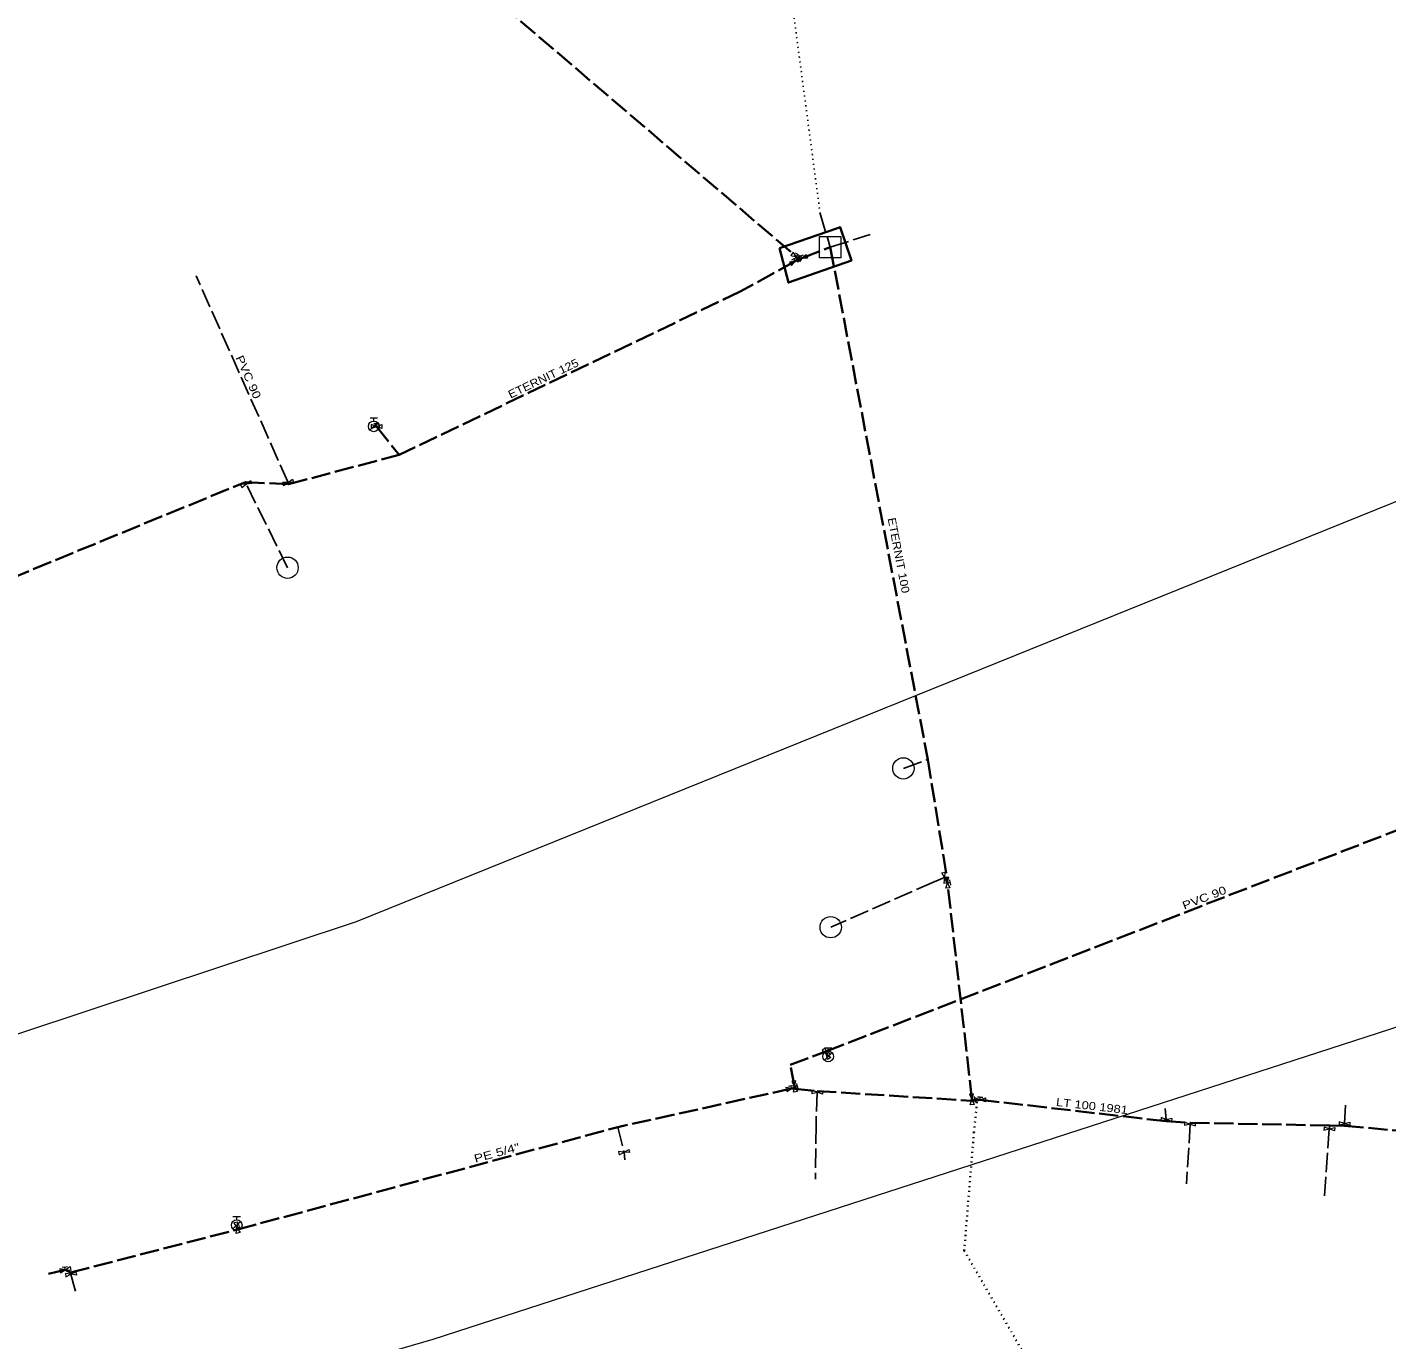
# Model space of a CAD drawing. Extents: x -616592 to -615844, y -1088988 to -1088174.
# Drawn here: x -616074.1 to -615946.8, y -1088431.2 to -1088308.2 of the extents above; entities that cross this region are included whole.
import ezdxf
from ezdxf.enums import TextEntityAlignment as Align

# ---------------------------------------------------------------- set-up
doc = ezdxf.new("R2010")
doc.units = 0
doc.header["$LTSCALE"] = 0.3
for name, pattern in [('DOTTED', [1.5, 0.3, -1.2]), ('LONG_DASHED', [7.5, 6, -1.5]), ('SHORT_DASHED', [2.7, 1.5, -1.2])]:
    doc.linetypes.add(name, pattern=pattern)
for name, color, linetype, lineweight in [('1', 7, 'Continuous', 13), ('10', 7, 'Continuous', 13), ('35', 7, 'LONG_DASHED', 35), ('36', 7, 'SHORT_DASHED', 35), ('50', 7, 'LONG_DASHED', 25), ('51', 7, 'SHORT_DASHED', 25), ('56', 7, 'Continuous', 35)]:
    doc.layers.add(name, color=color, linetype=linetype, lineweight=lineweight)
doc.layers.add('16', color=7, linetype='Continuous')
doc.layers.add('19', color=7, linetype='Continuous')

msp = doc.modelspace()

# ---------------------------------------------------------------- linework, layer by layer
at = {"layer": '1'}
msp.add_lwpolyline([(-616317.402, -1088743.479), (-616316.925, -1088623.142), (-616336.026, -1088584.94), (-616318.357, -1088562.497), (-616286.363, -1088552.469), (-616214.734, -1088468.424), (-616144.06, -1088425.447), (-616043.302, -1088392.02), (-615921.533, -1088342.835), (-615901, -1088273.116), (-615900.045, -1088185.251), (-615900.045, -1088185.251), (-615851.337, -1088190.027), (-615863.753, -1088293.172), (-615879.033, -1088367.189), (-615932.994, -1088397.75), (-616036.139, -1088431.177), (-616143.105, -1088462.216), (-616202.318, -1088518.087), (-616257.711, -1088587.328), (-616274.902, -1088683.788)], dxfattribs=at)
at = {"layer": '10'}
for p, q in [((-616002.31, -1088329.928), (-616002.527, -1088330.052)), ((-616001.936, -1088329.536), (-616002.145, -1088329.398)), ((-616001.648, -1088329.651), (-616001.879, -1088329.745)), ((-616042.024, -1088345.984), (-616041.317, -1088345.277)), ((-616042.02, -1088344.83), (-616041.32, -1088344.83)), ((-616041.67, -1088345.13), (-616041.67, -1088344.83)), ((-616041.41, -1088345.4), (-616041.66, -1088345.4)), ((-615987.671, -1088388.356), (-615987.696, -1088388.107)), ((-615999.45, -1088403.86), (-615998.75, -1088403.86)), ((-615999.034, -1088404.293), (-615999.161, -1088404.078)), ((-615999.1, -1088404.16), (-615999.1, -1088403.86)), ((-615999.454, -1088405.014), (-615998.747, -1088404.307)), ((-616002.566, -1088407.424), (-616002.812, -1088407.47)), ((-616001.994, -1088407.428), (-616002.036, -1088407.181)), ((-615985.381, -1088408.663), (-615985.398, -1088408.413)), ((-615984.85, -1088408.48), (-615985.1, -1088408.48)), ((-616054.864, -1088420.824), (-616054.157, -1088420.117)), ((-616054.86, -1088419.67), (-616054.16, -1088419.67)), ((-616054.51, -1088419.97), (-616054.51, -1088419.67)), ((-616054.246, -1088420.656), (-616054.299, -1088420.412)), ((-616070.624, -1088424.396), (-616070.868, -1088424.449))]:
    msp.add_line(p, q, dxfattribs=at)
for points in [[(-615997.9, -1088327.84), (-615997.9, -1088329.84), (-615999.9, -1088329.84), (-615999.9, -1088327.84)], [(-616053.63, -1088351.03), (-616053.215, -1088350.713), (-616053.109, -1088350.994), (-616053.63, -1088351.03), (-616054.151, -1088351.066), (-616054.045, -1088351.347)], [(-616049.7, -1088350.88), (-616049.272, -1088350.581), (-616049.178, -1088350.866), (-616049.7, -1088350.88), (-616050.222, -1088350.894), (-616050.128, -1088351.179)], [(-615988.21, -1088387.91), (-615988.449, -1088387.446), (-615988.154, -1088387.391), (-615988.21, -1088387.91), (-615988.266, -1088388.429), (-615987.971, -1088388.374)], [(-616000.13, -1088408.01), (-615999.622, -1088407.891), (-615999.64, -1088408.19), (-616000.13, -1088408.01), (-616000.62, -1088407.83), (-616000.638, -1088408.129)], [(-615967.42, -1088410.56), (-615966.91, -1088410.448), (-615966.933, -1088410.747), (-615967.42, -1088410.56), (-615967.907, -1088410.373), (-615967.93, -1088410.672)], [(-615965.17, -1088410.99), (-615965.673, -1088411.13), (-615965.667, -1088410.83), (-615965.17, -1088410.99), (-615964.673, -1088411.15), (-615964.667, -1088410.85)], [(-615952.14, -1088411.45), (-615951.633, -1088411.326), (-615951.649, -1088411.626), (-615952.14, -1088411.45), (-615952.631, -1088411.274), (-615952.647, -1088411.574)], [(-615950.71, -1088410.95), (-615950.205, -1088410.819), (-615950.216, -1088411.119), (-615950.71, -1088410.95), (-615951.204, -1088410.781), (-615951.215, -1088411.081)], [(-616018.22, -1088413.62), (-616017.759, -1088413.375), (-616017.7, -1088413.669), (-616018.22, -1088413.62), (-616018.74, -1088413.571), (-616018.681, -1088413.865)], [(-616070.05, -1088425.07), (-616069.58, -1088424.842), (-616069.532, -1088425.138), (-616070.05, -1088425.07), (-616070.568, -1088425.002), (-616070.52, -1088425.298)]]:
    msp.add_lwpolyline(points, close=True, dxfattribs=at)
for points in [[(-616002.186, -1088330.145), (-616001.844, -1088329.735), (-616001.659, -1088330.06), (-616002.186, -1088330.145), (-616002.713, -1088330.23), (-616002.528, -1088330.555), (-616002.186, -1088330.145), (-616002.31, -1088329.928), (-616002.093, -1088329.804)], [(-616002.074, -1088329.745), (-616001.554, -1088329.865), (-616001.76, -1088330.177), (-616002.074, -1088329.745), (-616002.388, -1088329.313), (-616002.595, -1088329.625), (-616002.074, -1088329.745), (-616001.936, -1088329.536), (-616001.728, -1088329.674)], [(-616001.554, -1088329.883), (-616001.16, -1088329.523), (-616001.02, -1088329.869), (-616001.554, -1088329.883), (-616002.088, -1088329.897), (-616001.948, -1088330.243), (-616001.554, -1088329.883), (-616001.648, -1088329.651), (-616001.416, -1088329.558)], [(-616041.41, -1088345.65), (-616040.91, -1088345.463), (-616040.91, -1088345.837), (-616041.41, -1088345.65), (-616041.91, -1088345.463), (-616041.91, -1088345.837), (-616041.41, -1088345.65), (-616041.41, -1088345.4), (-616041.16, -1088345.4)], [(-615987.92, -1088388.38), (-615987.685, -1088388.859), (-615988.057, -1088388.896), (-615987.92, -1088388.38), (-615987.783, -1088387.864), (-615988.155, -1088387.901), (-615987.92, -1088388.38), (-615987.671, -1088388.356), (-615987.647, -1088388.604)], [(-615999.25, -1088404.42), (-615998.835, -1088404.756), (-615999.158, -1088404.946), (-615999.25, -1088404.42), (-615999.342, -1088403.894), (-615999.665, -1088404.084), (-615999.25, -1088404.42), (-615999.034, -1088404.293), (-615998.908, -1088404.509)], [(-616002.52, -1088407.67), (-616002.063, -1088407.394), (-616001.994, -1088407.762), (-616002.52, -1088407.67), (-616003.046, -1088407.578), (-616002.977, -1088407.946), (-616002.52, -1088407.67), (-616002.566, -1088407.424), (-616002.32, -1088407.378)], [(-616002.24, -1088407.47), (-616001.971, -1088407.931), (-616002.34, -1088407.994), (-616002.24, -1088407.47), (-616002.14, -1088406.946), (-616002.509, -1088407.009), (-616002.24, -1088407.47), (-616001.994, -1088407.428), (-616001.951, -1088407.674)], [(-615985.63, -1088408.68), (-615985.409, -1088409.166), (-615985.782, -1088409.192), (-615985.63, -1088408.68), (-615985.478, -1088408.168), (-615985.851, -1088408.194), (-615985.63, -1088408.68), (-615985.381, -1088408.663), (-615985.363, -1088408.912)], [(-615984.85, -1088408.73), (-615984.35, -1088408.543), (-615984.35, -1088408.917), (-615984.85, -1088408.73), (-615985.35, -1088408.543), (-615985.35, -1088408.917), (-615984.85, -1088408.73), (-615984.85, -1088408.48), (-615984.6, -1088408.48)], [(-616054.49, -1088420.71), (-616054.2, -1088421.158), (-616054.565, -1088421.238), (-616054.49, -1088420.71), (-616054.415, -1088420.182), (-616054.78, -1088420.262), (-616054.49, -1088420.71), (-616054.246, -1088420.656), (-616054.192, -1088420.901)], [(-616070.57, -1088424.64), (-616070.122, -1088424.35), (-616070.042, -1088424.715), (-616070.57, -1088424.64), (-616071.098, -1088424.565), (-616071.018, -1088424.93), (-616070.57, -1088424.64), (-616070.624, -1088424.396), (-616070.379, -1088424.342)]]:
    msp.add_lwpolyline(points, dxfattribs=at)
for centre, radius in [((-616041.6698, -1088345.6297), 0.5), ((-616049.75, -1088358.87), 1), ((-615992.05, -1088377.67), 1), ((-615998.86, -1088392.55), 1), ((-615999.0998, -1088404.6597), 0.5), ((-616054.5098, -1088420.4697), 0.5)]:
    msp.add_circle(centre, radius, dxfattribs=at)
at = {"layer": '35'}
for p, q in [((-615998.9, -1088328.84), (-615989.76, -1088376.84)), ((-616041.67, -1088345.63), (-616041.41, -1088345.65)), ((-616041.41, -1088345.65), (-616039.3, -1088348.31)), ((-616049.66, -1088351.04), (-616039.3, -1088348.31)), ((-616104.798, -1088371.828), (-616053.69, -1088350.85)), ((-616053.69, -1088350.85), (-616049.66, -1088351.04)), ((-615999.31, -1088404.19), (-615929.43, -1088377.13)), ((-615989.76, -1088376.84), (-615987.98, -1088387.85)), ((-616002.21, -1088407.71), (-616002.24, -1088407.47)), ((-616002.21, -1088407.71), (-616000.13, -1088407.91)), ((-616000.13, -1088407.91), (-615985.64, -1088408.81)), ((-615985.64, -1088408.81), (-615985.13, -1088408.73)), ((-616054.44, -1088420.88), (-616018.79, -1088411.28)), ((-615967.44, -1088410.73), (-615965.17, -1088410.87)), ((-615965.17, -1088410.87), (-615952.1, -1088411.13)), ((-615952.1, -1088411.13), (-615950.72, -1088411.16)), ((-616054.49, -1088420.71), (-616054.51, -1088420.47)), ((-616054.44, -1088420.88), (-616054.49, -1088420.71)), ((-616070.08, -1088424.91), (-616054.44, -1088420.88)), ((-616070.57, -1088424.64), (-616072.15, -1088425.04)), ((-616070.08, -1088424.91), (-616070.57, -1088424.64))]:
    msp.add_line(p, q, dxfattribs=at)
for points in [[(-616094.121, -1088249.2), (-616041.605, -1088295.97), (-616001.79, -1088329.97)], [(-616001.79, -1088329.97), (-616001.554, -1088329.883), (-615998.9, -1088328.84)], [(-616001.79, -1088329.97), (-616002.186, -1088330.145), (-616007.34, -1088333), (-616039.3, -1088348.31)], [(-615985.64, -1088408.81), (-615985.63, -1088408.68), (-615987.92, -1088388.38), (-615987.98, -1088387.85)], [(-616002.24, -1088407.47), (-616002.66, -1088405.46), (-615999.31, -1088404.19)], [(-615999.31, -1088404.19), (-615999.25, -1088404.42), (-615999.1, -1088404.66)], [(-616002.21, -1088407.71), (-616002.52, -1088407.67), (-616018.79, -1088411.28)], [(-615967.44, -1088410.73), (-615984.85, -1088408.73), (-615985.13, -1088408.73)], [(-615950.72, -1088411.16), (-615912.516, -1088414.608), (-615902.96, -1088415.47)]]:
    msp.add_lwpolyline(points, dxfattribs=at)
at = {"layer": '36', "linetype": 'DOTTED'}
msp.add_line((-615986.346, -1088422.861), (-615949.1, -1088487.052), dxfattribs=at)
msp.add_lwpolyline([(-615986.346, -1088422.861), (-615985.44, -1088411.78), (-615985.13, -1088408.73)], dxfattribs=at)
at = {"layer": '50'}
for p, q in [((-615999.85, -1088325.68), (-615998.9, -1088328.84)), ((-615998.9, -1088328.84), (-615995.15, -1088327.66)), ((-616049.7, -1088350.88), (-616058.31, -1088331.54)), ((-616049.66, -1088351.04), (-616049.7, -1088350.88)), ((-615992.05, -1088377.67), (-615989.76, -1088376.84)), ((-615987.98, -1088387.85), (-615988.21, -1088387.91)), ((-615950.71, -1088410.95), (-615950.635, -1088409.222)), ((-615967.42, -1088410.56), (-615967.531, -1088409.545)), ((-615967.44, -1088410.73), (-615967.42, -1088410.56)), ((-616018.79, -1088411.28), (-616018.22, -1088413.62)), ((-615965.17, -1088410.99), (-615965.532, -1088416.608)), ((-615965.17, -1088410.87), (-615965.17, -1088410.99)), ((-615952.14, -1088411.45), (-615952.596, -1088418.02)), ((-615952.1, -1088411.13), (-615952.14, -1088411.45)), ((-615950.72, -1088411.16), (-615950.71, -1088410.95)), ((-616018.22, -1088413.62), (-616018.146, -1088414.355)), ((-616070.08, -1088424.91), (-616070.05, -1088425.07))]:
    msp.add_line(p, q, dxfattribs=at)
for points in [[(-616049.75, -1088358.87), (-616053.63, -1088351.03), (-616053.69, -1088350.85)], [(-615988.21, -1088387.91), (-615989.17, -1088388.29), (-615998.86, -1088392.55)], [(-616000.13, -1088407.91), (-616000.13, -1088408.01), (-616000.23, -1088411.05), (-616000.286, -1088416.156)], [(-616070.05, -1088425.07), (-616069.8, -1088426.01), (-616069.616, -1088426.639)]]:
    msp.add_lwpolyline(points, dxfattribs=at)
at = {"layer": '51', "linetype": 'DOTTED'}
msp.add_lwpolyline([(-615999.85, -1088325.68), (-616005.733, -1088281.458), (-616006.619, -1088241.469)], dxfattribs=at)
at = {"layer": '56'}
msp.add_lwpolyline([(-616003.661, -1088328.939), (-615998.305, -1088327.079), (-615997.958, -1088326.98), (-615996.922, -1088330.103), (-616002.824, -1088332.161)], close=True, dxfattribs=at)

# ---------------------------------------------------------------- texts
at = {"layer": '16'}
for s, rotation, width, p in [('ETERNIT 125', 25.596, 1.15, (-616025.622, -1088341.4805)), ('ETERNIT 100', 280.781, 1.15, (-615992.8529, -1088357.7834)), ('PVC 90', 21.168, 1.25, (-615963.7174, -1088390.1391)), ('LT 100 1981', 353.447, 1.2, (-615974.4168, -1088409.6768)), ('PE 5/4"', 15.071, 1.3, (-616030.0425, -1088414.0506))]:
    msp.add_text(s, height=0.75, rotation=rotation, dxfattribs=dict(at, width=width)).set_placement(p, align=Align.CENTER)
at = {"layer": '19', "width": 1.25}
msp.add_text('PVC 90', height=0.75, rotation=293.998, dxfattribs=at).set_placement((-616053.7542, -1088341.1585), align=Align.CENTER)

doc.saveas('drawing.dxf')
